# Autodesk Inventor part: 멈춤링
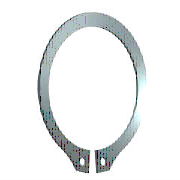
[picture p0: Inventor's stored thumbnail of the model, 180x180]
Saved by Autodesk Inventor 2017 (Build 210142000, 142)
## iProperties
IsCustomPart: 1
Created: 2012-02
Part Number: 멈춤링
Material: 강철, 연강
Description: 리테이닝 링(C형)
Document SubType Name: Modeling
Standard: KS B 1336
Designer: mduedu
Standards Organization: KS
Language: ko-KR
Size Designation: 20 x 1.2
Categories: <MemberInstance><Categories><Category DisplayName="샤프트 부품" InternalName="7f7aeb1f-a693-4053-b835-cee3144e0d98" Mnemonic="SHFT"><Category DisplayName="써클립" Inter
Density: 7.85 g/cm^3
Mass: 1.66335 g
Surface Area: 5.4075 cm^2
Volume: 0.211892 cm^3
Appearance: 노란색
Author: mduedu
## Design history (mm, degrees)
sketch "스케치1"
  geometry: L1 (-6, 0)-(6, 0) reference; L2 (0, 20.189)-(0, -80.536) reference; L3 (-48.09, 0)-(48.09, 0) reference; L4 (-0.5, -19.487)-(-0.5, -23.387); L5 (-0.5, -6.54)-(-0.5, -13.29); L6 (-2.795, 2.7)-(3.672, 2.7); L7 (0.5, -6.54)-(0.5, -13.29); L8 (0.5, -19.487)-(0.5, -23.387); C1 r 1 at (-2, -21.219); C2 r 1 at (2, -21.219); A1 r 9.5 centre (0, -10) between (0.5, -19.487) and (-0.5, -19.487); A2 r 12.025 centre (0, -9.325) between (5.071, -20.228) and (-5.071, -20.228); A3 r 13.396 centre (0, -10) between (-2.351, -23.188) and (-0.5, -23.387); A4 r 2 centre (-2, -21.219) between (-3.957, -21.631) and (-2.351, -23.188); A5 r 2 centre (-5.915, -22.042) between (-3.957, -21.631) and (-5.071, -20.228); A6 r 2 centre (5.915, -22.042) between (5.071, -20.228) and (3.957, -21.631); A7 r 2 centre (2, -21.219) between (2.351, -23.188) and (3.957, -21.631); A8 r 13.396 centre (0, -10) between (0.5, -23.387) and (2.351, -23.188)
  constraints: 16 point on circle, 12 end point, 10 centre point, 9 symmetric about line, 5 point on line, 4 tangent, 3 coincident, 2 horizontal, 1 perpendicular, 1 vertical, 5 other
  dimensions: "d0" = 19 diameter of A1 (= ND); "d1" = 3.9 distance of L4.end L4.start (= SRB2); "d6" = 0.5 distance between parallel lines of L2 L5 (= 0.25 x SD5); "d7" = 2.7 distance between parallel lines of L6 L3 (= SRB1); "d8" = 0.675 distance of A1.centre A2.centre (= 0.25 x SRB1); "d9" = 2 radius of A4 (= SD5); "d10" = 2 radius of A5 (= SD5); "d11" = 1.5 distance from line of L4 A4.centre (= 0.75 x SD5); "d12" = 2 diameter of C1 (= SD5); "d13" = 2 diameter of C2 (= SD5); "d14" = 10 distance from line of A1.centre L1 (= 0.5 x WD)
extrude "본체" new body sketch "스케치1" distance "d2" = 1.2 (= SD); taper "d3" = 0 deg
workaxis "Work Axis1"
workplane "Work Plane1"
body "Solid1"
other parameters: "SD" = 1.2 [user parameter; used in 1 equation term], "SRB1" = 2.7 [user parameter; used in 2 equation terms], "ND" = 19 [user parameter; used in 1 equation term], "SRB2" = 3.9 [user parameter; used in 1 equation term], "SD5" = 2 [user parameter; used in 6 equation terms], "d15" = 0, "d16" = 0, "d17" = 0, "d41" = 0, "d42" = 0, "SD3" = 18.5 [user parameter], "WDMAX" = 21 [user parameter]
